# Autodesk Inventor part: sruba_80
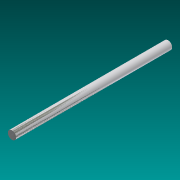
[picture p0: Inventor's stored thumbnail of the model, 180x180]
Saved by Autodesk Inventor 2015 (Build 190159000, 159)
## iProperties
Created: 2016-02
Part Number: sruba_80
Material: Generic
Document SubType Name: Modeling
Designer: Rafał
Density: 1 g/cm^3
Appearance: Aluminum - Polished
Author: Rafał
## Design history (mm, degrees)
sketch "Sketch1"
  geometry: C1 r 4 at (0, 0); 1 further point
  constraints: 1 centre point, 1 coincident
  dimensions: "d0" = 8 diameter of C1
extrude "Extrusion1" new body sketch "Sketch1" distance "d1" = 150; taper "d2" = 0 deg
body "Solid1"
